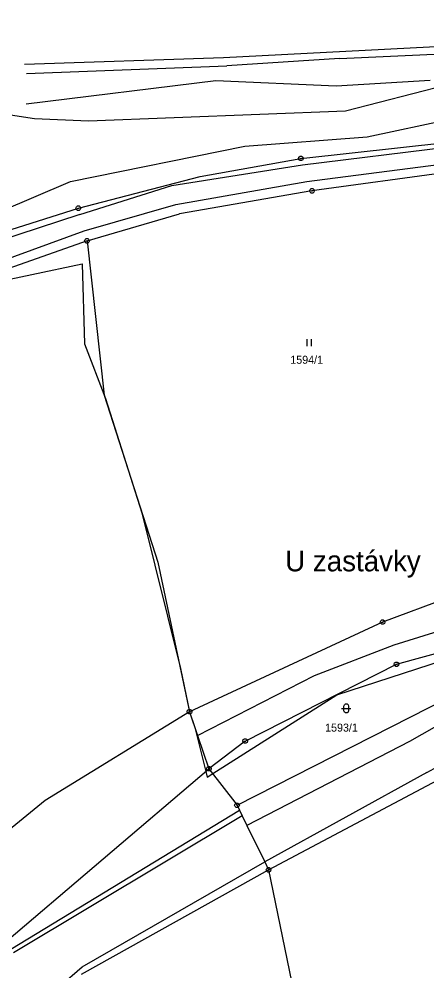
# Model space of a CAD drawing. Extents: x -806774 to -803680, y -1151731 to -1150053.
# Drawn here: x -806342.9 to -806256.3, y -1150802.6 to -1150600.5 of the extents above; entities that cross this region are included whole.
import ezdxf

# ---------------------------------------------------------------- set-up
doc = ezdxf.new("R2010")
doc.units = 0
for name, color, linetype in [('1', 7, 'Continuous'), ('11', 7, 'Continuous'), ('2', 7, 'Continuous'), ('3', 7, 'Continuous'), ('4', 7, 'Continuous'), ('6', 7, 'Continuous'), ('7', 7, 'Continuous'), ('8', 7, 'Continuous')]:
    doc.layers.add(name, color=color, linetype=linetype)

msp = doc.modelspace()

# ---------------------------------------------------------------- linework, layer by layer
at = {"layer": '1'}
for p, q in [((-806244.76, -1150605.88), (-806299.51, -1150608.72)), ((-806299.51, -1150608.72), (-806341.75, -1150610.16)), ((-806252.2, -1150614.52), (-806273.63, -1150620.09)), ((-806339.68, -1150621.7), (-806362.9, -1150618.04)), ((-806273.63, -1150620.09), (-806328.18, -1150622.16)), ((-806328.18, -1150622.16), (-806339.68, -1150621.7)), ((-806283.12, -1150630.1), (-806250.44, -1150626.52)), ((-806304.45, -1150633.91), (-806283.12, -1150630.1)), ((-806330.33, -1150640.68), (-806304.45, -1150633.91)), ((-806248.8, -1150632.62), (-806280.75, -1150636.99)), ((-806280.75, -1150636.99), (-806308.87, -1150641.88)), ((-806359.65, -1150649.99), (-806330.33, -1150640.68)), ((-806328.5, -1150647.6), (-806308.87, -1150641.88)), ((-806328.5, -1150647.6), (-806357.29, -1150657.74)), ((-806328.5, -1150647.6), (-806324.83, -1150680.36)), ((-806324.83, -1150680.36), (-806313.47, -1150715.84)), ((-806313.47, -1150715.84), (-806306.74, -1150747.59)), ((-806249.54, -1150722.51), (-806265.75, -1150728.56)), ((-806265.75, -1150728.56), (-806306.74, -1150747.59)), ((-806262.81, -1150737.51), (-806247.37, -1150733.21)), ((-806294.91, -1150753.82), (-806262.81, -1150737.51)), ((-806296.65, -1150767.46), (-806245.69, -1150741.47)), ((-806289.95, -1150781.17), (-806215.97, -1150741.78)), ((-806306.74, -1150747.59), (-806337.39, -1150766.46)), ((-806306.74, -1150747.59), (-806305.03, -1150752.61)), ((-806305.03, -1150752.61), (-806302.62, -1150759.69)), ((-806294.91, -1150753.82), (-806302.62, -1150759.69)), ((-806352.38, -1150802.05), (-806302.62, -1150759.69)), ((-806302.62, -1150759.69), (-806296.65, -1150767.46)), ((-806337.39, -1150766.46), (-806365.52, -1150789.31)), ((-806296.65, -1150767.46), (-806296.13, -1150768.51)), ((-806344.65, -1150798), (-806296.13, -1150768.51)), ((-806296.13, -1150768.51), (-806295.56, -1150769.69)), ((-806295.56, -1150769.69), (-806294.56, -1150771.74)), ((-806294.56, -1150771.74), (-806290.78, -1150779.48)), ((-806290.78, -1150779.48), (-806289.95, -1150781.17)), ((-806329.7, -1150803.3), (-806289.95, -1150781.17)), ((-806289.95, -1150781.17), (-806281.65, -1150821.69))]:
    msp.add_line(p, q, dxfattribs=at)
at = {"layer": '11'}
for points in [[(-806415.5, -1150704), (-806405.5, -1150672.5), (-806381.8, -1150658.35), (-806369.5, -1150651), (-806332, -1150635), (-806295, -1150627.5), (-806269, -1150625.5), (-806251.15, -1150621.7), (-806250, -1150621.46), (-806245.5, -1150620.5), (-806229.47, -1150620.33), (-806217.07, -1150620.19), (-806203.09, -1150620.04), (-806199, -1150620), (-806182.11, -1150618.1), (-806150, -1150614.5), (-806126.31, -1150609.23), (-806103.46, -1150604.16), (-806087, -1150600.5), (-806082.1, -1150600.8), (-806048.61, -1150602.81)], [(-806351, -1150657), (-806329.5, -1150652.5), (-806329, -1150669.5), (-806324.6, -1150681.08), (-806316.83, -1150705.36), (-806308.68, -1150738.42), (-806306.74, -1150747.59), (-806305.61, -1150750.92), (-806303.3, -1150760.27), (-806303, -1150761.5), (-806301.81, -1150760.74), (-806275.5, -1150744), (-806250, -1150735.75)]]:
    msp.add_lwpolyline(points, dxfattribs=at)
at = {"layer": '3'}
for p, q in [((-806281.87, -1150668.48), (-806281.87, -1150669.98)), ((-806280.87, -1150669.98), (-806280.87, -1150668.48))]:
    msp.add_line(p, q, dxfattribs=at)
msp.add_lwpolyline([(-806274.47, -1150746.88), (-806273.2, -1150746.88), (-806272.47, -1150746.88)], dxfattribs=at)
msp.add_lwpolyline([(-806273.97, -1150746.38), (-806273.87, -1150746.09), (-806273.62, -1150745.91), (-806273.31, -1150745.91), (-806273.06, -1150746.09), (-806272.96, -1150746.38), (-806272.96, -1150747.38), (-806273.06, -1150747.67), (-806273.31, -1150747.85), (-806273.62, -1150747.85), (-806273.87, -1150747.67), (-806273.97, -1150747.38)], close=True, dxfattribs=at)
at = {"layer": '4'}
for p, q in [((-806274.94, -1150608.85), (-806245.38, -1150607.51)), ((-806274.94, -1150608.85), (-806298.81, -1150610.43)), ((-806341.35, -1150612.04), (-806298.81, -1150610.43)), ((-806341.44, -1150618.49), (-806301.13, -1150613.53)), ((-806301.13, -1150613.53), (-806275.59, -1150614.69)), ((-806275.59, -1150614.69), (-806255.69, -1150613.46)), ((-806282.75, -1150631.45), (-806250.18, -1150627.48)), ((-806310.47, -1150635.87), (-806282.75, -1150631.45)), ((-806281.82, -1150635.03), (-806249.25, -1150630.75)), ((-806330, -1150641.99), (-806310.47, -1150635.87)), ((-806309.63, -1150639.91), (-806281.82, -1150635.03)), ((-806329.14, -1150645.5), (-806309.63, -1150639.91)), ((-806330, -1150641.99), (-806358.81, -1150651.4)), ((-806357.79, -1150655.89), (-806329.14, -1150645.5)), ((-806242.07, -1150743.68), (-806260.05, -1150753.93)), ((-806256.37, -1150760.46), (-806238.47, -1150750.73)), ((-806260.05, -1150753.93), (-806294.56, -1150771.74)), ((-806256.37, -1150760.46), (-806290.78, -1150779.48)), ((-806295.56, -1150769.69), (-806344.11, -1150798.77)), ((-806329.54, -1150801.75), (-806290.78, -1150779.48)), ((-806334.29, -1150805.84), (-806329.54, -1150801.75))]:
    msp.add_line(p, q, dxfattribs=at)
at = {"layer": '6'}
for p, q in [((-806263.33, -1150733.35), (-806239.37, -1150726.01)), ((-806280.22, -1150739.9), (-806263.33, -1150733.35)), ((-806305.03, -1150752.61), (-806280.22, -1150739.9))]:
    msp.add_line(p, q, dxfattribs=at)
at = {"layer": '8'}
for p, q in [((-806283.24, -1150630.1), (-806283, -1150630.1)), ((-806280.87, -1150636.99), (-806280.63, -1150636.99)), ((-806330.45, -1150640.68), (-806330.21, -1150640.68)), ((-806328.62, -1150647.6), (-806328.38, -1150647.6)), ((-806265.87, -1150728.56), (-806265.63, -1150728.56)), ((-806262.93, -1150737.51), (-806262.69, -1150737.51)), ((-806306.86, -1150747.59), (-806306.62, -1150747.59)), ((-806295.03, -1150753.82), (-806294.79, -1150753.82)), ((-806302.74, -1150759.69), (-806302.5, -1150759.69)), ((-806296.77, -1150767.46), (-806296.53, -1150767.46)), ((-806290.07, -1150781.17), (-806289.83, -1150781.17))]:
    msp.add_line(p, q, dxfattribs=at)
for points in [[(-806282.97, -1150629.62), (-806282.72, -1150629.8), (-806282.62, -1150630.09), (-806282.72, -1150630.38), (-806282.97, -1150630.56), (-806283.28, -1150630.56), (-806283.53, -1150630.38), (-806283.63, -1150630.09), (-806283.53, -1150629.8), (-806283.28, -1150629.62)], [(-806280.6, -1150636.51), (-806280.35, -1150636.69), (-806280.25, -1150636.98), (-806280.35, -1150637.27), (-806280.6, -1150637.45), (-806280.91, -1150637.45), (-806281.16, -1150637.27), (-806281.26, -1150636.98), (-806281.16, -1150636.69), (-806280.91, -1150636.51)], [(-806330.18, -1150640.2), (-806329.93, -1150640.38), (-806329.83, -1150640.67), (-806329.93, -1150640.96), (-806330.18, -1150641.14), (-806330.49, -1150641.14), (-806330.74, -1150640.96), (-806330.84, -1150640.67), (-806330.74, -1150640.38), (-806330.49, -1150640.2)], [(-806328.35, -1150647.12), (-806328.1, -1150647.3), (-806328, -1150647.59), (-806328.1, -1150647.88), (-806328.35, -1150648.06), (-806328.66, -1150648.06), (-806328.91, -1150647.88), (-806329.01, -1150647.59), (-806328.91, -1150647.3), (-806328.66, -1150647.12)], [(-806265.6, -1150728.08), (-806265.35, -1150728.26), (-806265.25, -1150728.55), (-806265.35, -1150728.84), (-806265.6, -1150729.02), (-806265.91, -1150729.02), (-806266.16, -1150728.84), (-806266.26, -1150728.55), (-806266.16, -1150728.26), (-806265.91, -1150728.08)], [(-806262.66, -1150737.03), (-806262.41, -1150737.21), (-806262.31, -1150737.5), (-806262.41, -1150737.79), (-806262.66, -1150737.97), (-806262.97, -1150737.97), (-806263.22, -1150737.79), (-806263.32, -1150737.5), (-806263.22, -1150737.21), (-806262.97, -1150737.03)], [(-806306.59, -1150747.11), (-806306.34, -1150747.29), (-806306.24, -1150747.58), (-806306.34, -1150747.87), (-806306.59, -1150748.05), (-806306.9, -1150748.05), (-806307.15, -1150747.87), (-806307.25, -1150747.58), (-806307.15, -1150747.29), (-806306.9, -1150747.11)], [(-806294.76, -1150753.34), (-806294.51, -1150753.52), (-806294.41, -1150753.81), (-806294.51, -1150754.1), (-806294.76, -1150754.28), (-806295.07, -1150754.28), (-806295.32, -1150754.1), (-806295.42, -1150753.81), (-806295.32, -1150753.52), (-806295.07, -1150753.34)], [(-806302.47, -1150759.21), (-806302.22, -1150759.39), (-806302.12, -1150759.68), (-806302.22, -1150759.97), (-806302.47, -1150760.15), (-806302.78, -1150760.15), (-806303.03, -1150759.97), (-806303.13, -1150759.68), (-806303.03, -1150759.39), (-806302.78, -1150759.21)], [(-806296.5, -1150766.98), (-806296.25, -1150767.16), (-806296.15, -1150767.45), (-806296.25, -1150767.74), (-806296.5, -1150767.92), (-806296.81, -1150767.92), (-806297.06, -1150767.74), (-806297.16, -1150767.45), (-806297.06, -1150767.16), (-806296.81, -1150766.98)], [(-806289.8, -1150780.69), (-806289.55, -1150780.87), (-806289.45, -1150781.16), (-806289.55, -1150781.45), (-806289.8, -1150781.63), (-806290.11, -1150781.63), (-806290.36, -1150781.45), (-806290.46, -1150781.16), (-806290.36, -1150780.87), (-806290.11, -1150780.69)]]:
    msp.add_lwpolyline(points, close=True, dxfattribs=at)

# ---------------------------------------------------------------- texts
at = {"layer": '2'}
for s, p in [('1594/1', (-806285.35, -1150673.7)), ('1593/1', (-806277.96, -1150751.81))]:
    msp.add_text(s, height=1.7, dxfattribs=at).set_placement(p)
at = {"layer": '7'}
msp.add_text('U zastávky', height=4.4, dxfattribs=at).set_placement((-806286.44, -1150717.78))

doc.saveas('drawing.dxf')
